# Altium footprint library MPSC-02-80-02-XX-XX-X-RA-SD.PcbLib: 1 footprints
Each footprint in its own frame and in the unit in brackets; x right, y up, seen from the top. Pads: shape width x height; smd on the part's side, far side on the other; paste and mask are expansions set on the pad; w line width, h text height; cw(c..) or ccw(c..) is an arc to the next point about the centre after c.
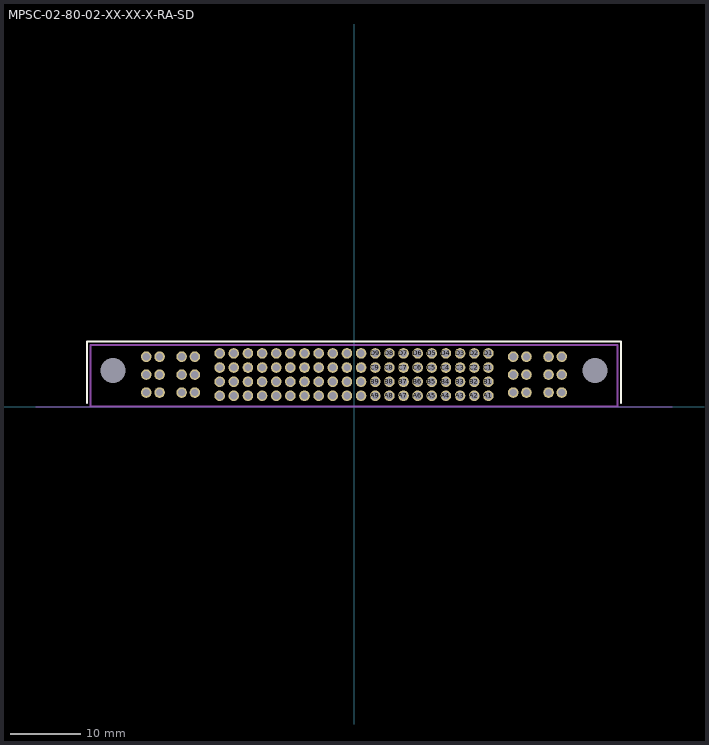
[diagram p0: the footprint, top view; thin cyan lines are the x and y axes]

## MPSC-02-80-02-XX-XX-X-RA-SD [mm]
pads (106):
  round 0 hole 3.56 unplated: 105(34.085,5.08) 106(-34.085,5.08)
  round 1.5 hole 1.04 mask+0.075: A1(19,1.52) A2(17,1.52) A3(15,1.52) A4(13,1.52) A5(11,1.52) A6(9,1.52) A7(7,1.52) A8(5,1.52) A9(3,1.52) A10(1,1.52) A11(-1,1.52) A12(-3,1.52) A13(-5,1.52) A14(-7,1.52) A15(-9,1.52) A16(-11,1.52) A17(-13,1.52) A18(-15,1.52) A19(-17,1.52) A20(-19,1.52) B1(19,3.52) B2(17,3.52) B3(15,3.52) B4(13,3.52) B5(11,3.52) B6(9,3.52) B7(7,3.52) B8(5,3.52) B9(3,3.52) B10(1,3.52) B11(-1,3.52) B12(-3,3.52) B13(-5,3.52) B14(-7,3.52) B15(-9,3.52) B16(-11,3.52) B17(-13,3.52) B18(-15,3.52) B19(-17,3.52) B20(-19,3.52) C1(19,5.52) C2(17,5.52) C3(15,5.52) C4(13,5.52) C5(11,5.52) C6(9,5.52) C7(7,5.52) C8(5,5.52) C9(3,5.52) C10(1,5.52) C11(-1,5.52) C12(-3,5.52) C13(-5,5.52) C14(-7,5.52) C15(-9,5.52) C16(-11,5.52) C17(-13,5.52) C18(-15,5.52) C19(-17,5.52) C20(-19,5.52) D1(19,7.52) D2(17,7.52) D3(15,7.52) D4(13,7.52) D5(11,7.52) D6(9,7.52) D7(7,7.52) D8(5,7.52) D9(3,7.52) D10(1,7.52) D11(-1,7.52) D12(-3,7.52) D13(-5,7.52) D14(-7,7.52) D15(-9,7.52) D16(-11,7.52) D17(-13,7.52) D18(-15,7.52) D19(-17,7.52) D20(-19,7.52) P1-1(29.39,1.98) P1-2(29.39,4.52) P1-3(29.39,7.06) P1-4(27.51,1.98) P1-5(27.51,4.52) P1-6(27.51,7.06) P2-1(24.39,1.98) P2-2(24.39,4.52) P2-3(24.39,7.06) P2-4(22.51,1.98) P2-5(22.51,4.52) P2-6(22.51,7.06) P3-1(-22.5,1.98) P3-2(-22.5,4.52) P3-3(-22.5,7.06) P3-4(-24.38,1.98) P3-5(-24.38,4.52) P3-6(-24.38,7.06) P4-1(-27.5,1.98) P4-2(-27.5,4.52) P4-3(-27.5,7.06) P4-4(-29.38,1.98) P4-5(-29.38,4.52) P4-6(-29.38,7.06)
Top Overlay:
  lines w0.254: -37.76,0.5 -37.76,9.21 37.76,9.21 37.76,0.5
Mechanical 1:
  lines w0.254: -37.26,0 37.26,0 37.26,8.71 -37.26,8.71 -37.26,0
  text "J1" at -0.446,-1.337 h0.76
Mechanical 16:
  lines w0.01: -45,0 45,0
